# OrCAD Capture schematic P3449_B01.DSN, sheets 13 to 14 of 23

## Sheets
13 0010_USB3.1 Type-A x2 (B): size Custom
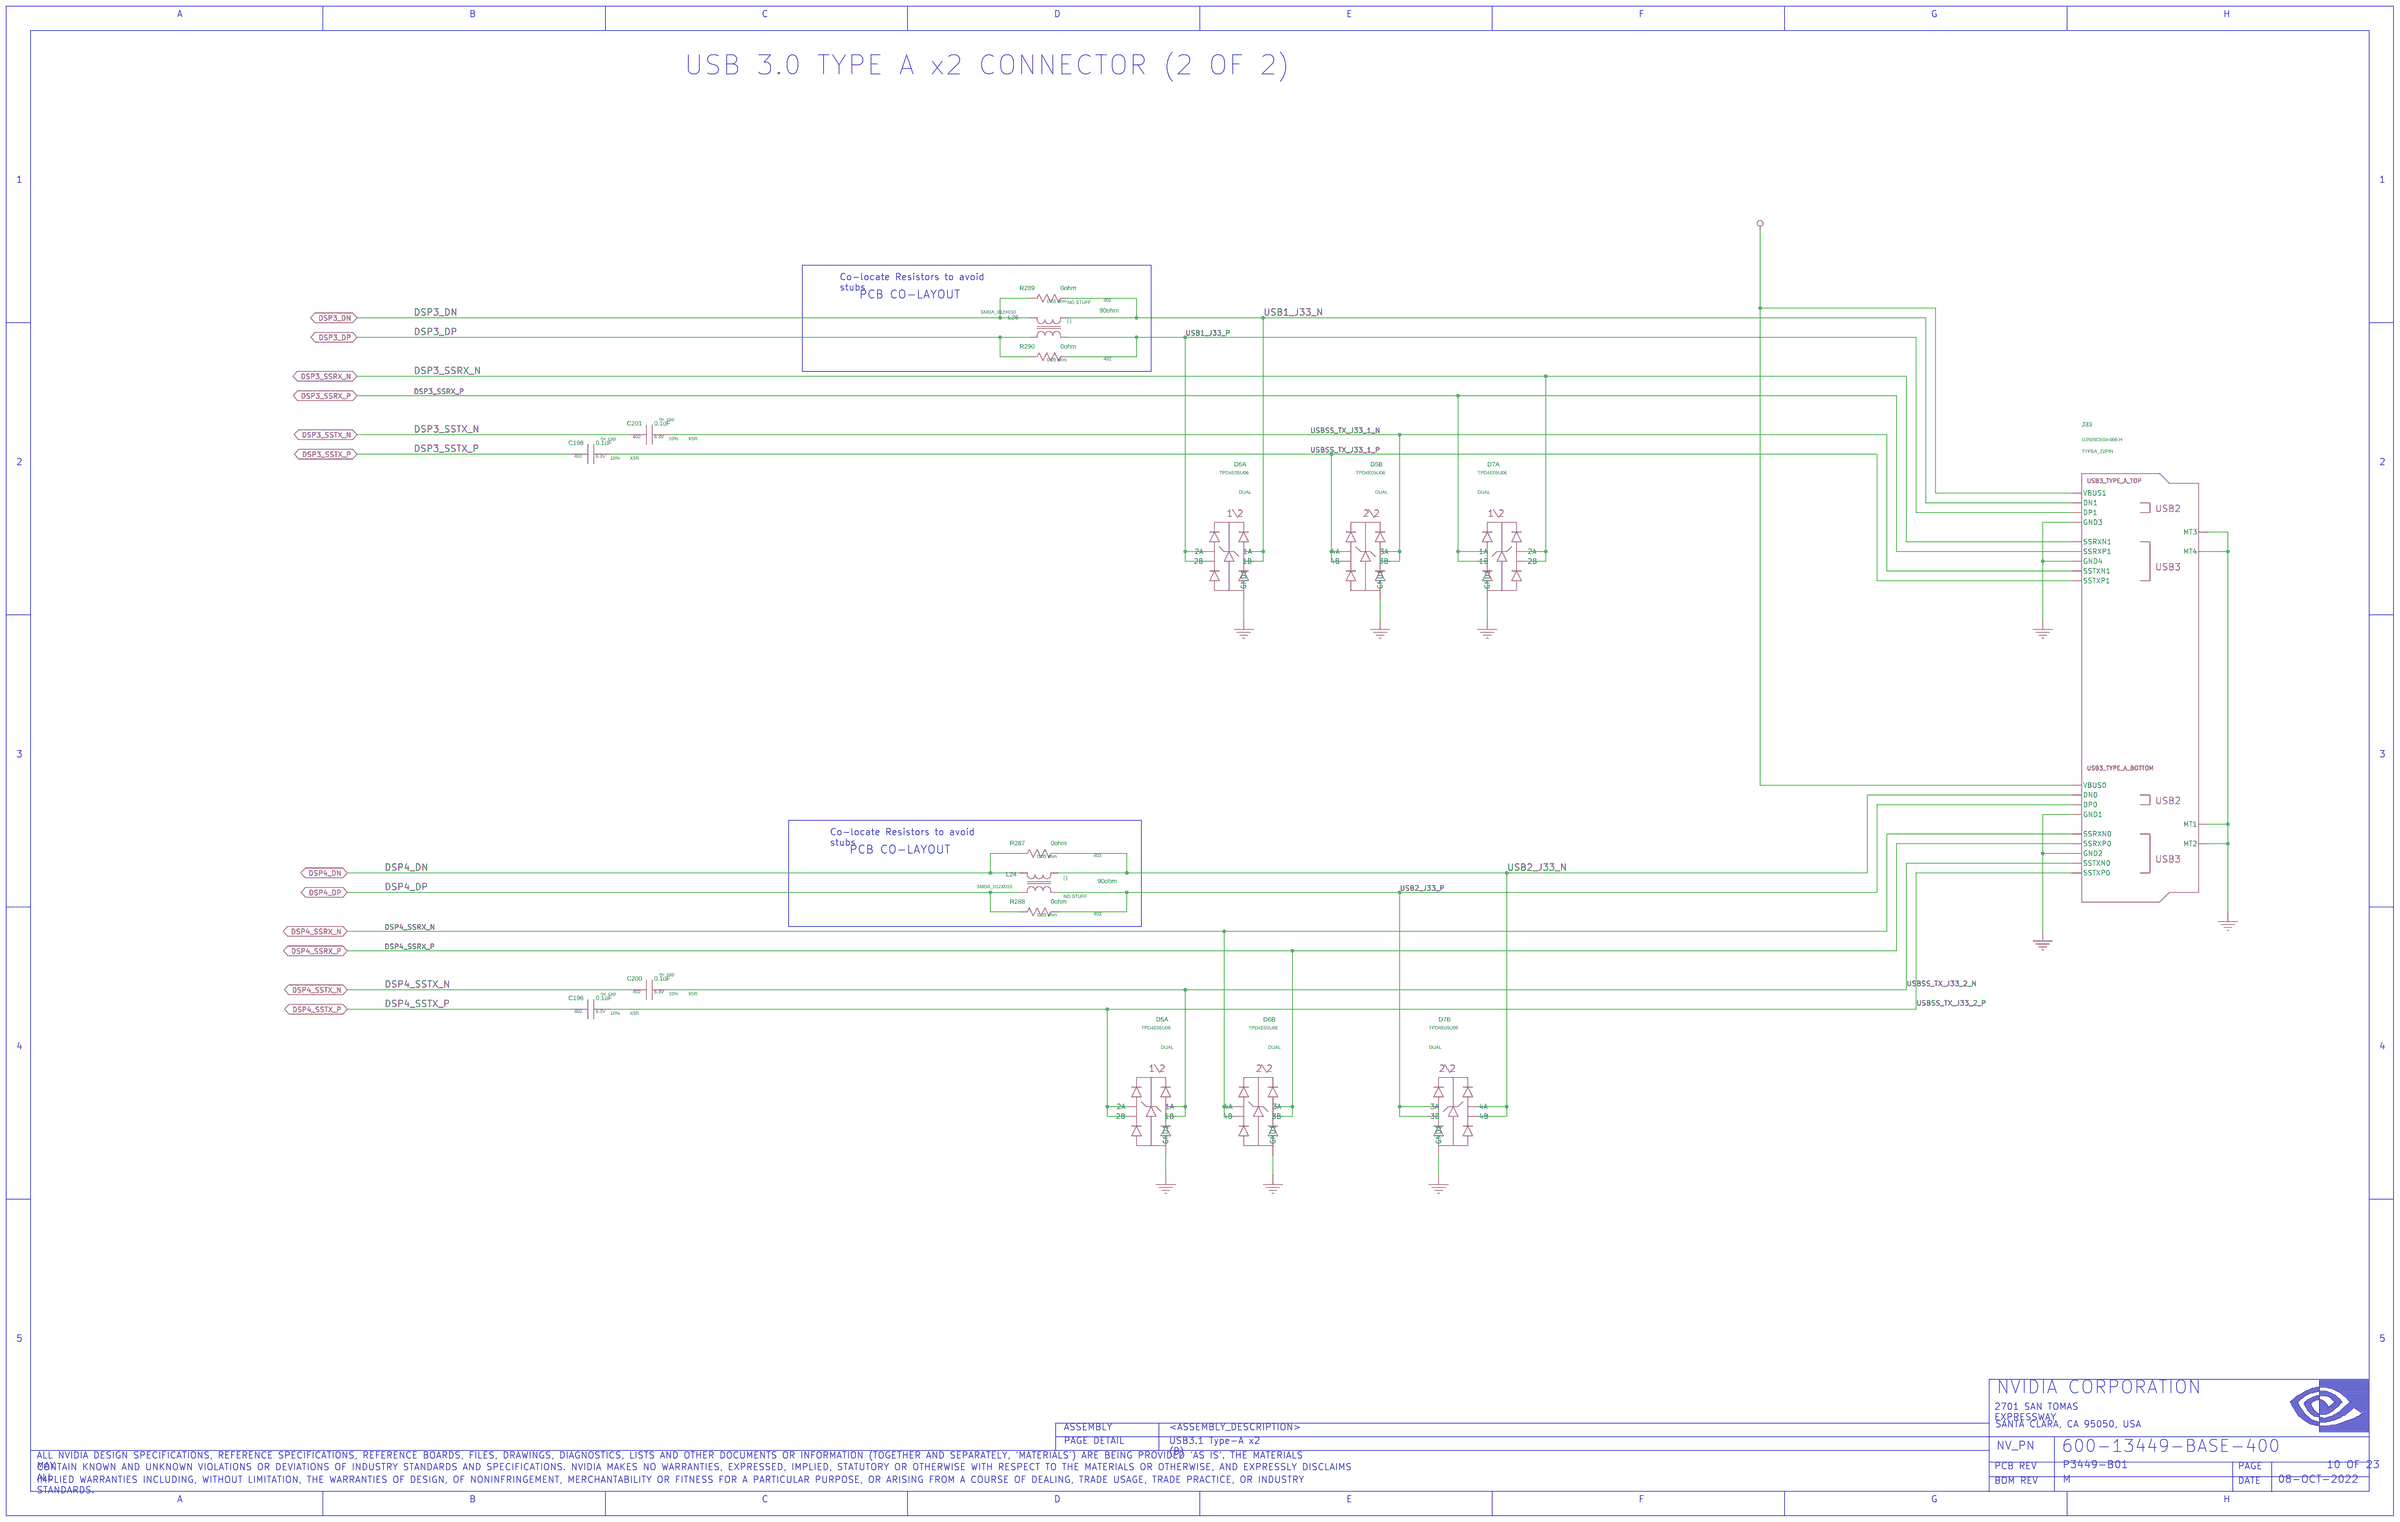
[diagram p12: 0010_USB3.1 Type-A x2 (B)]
14 0009_USB3.1 Type-A x2 (A): size Custom
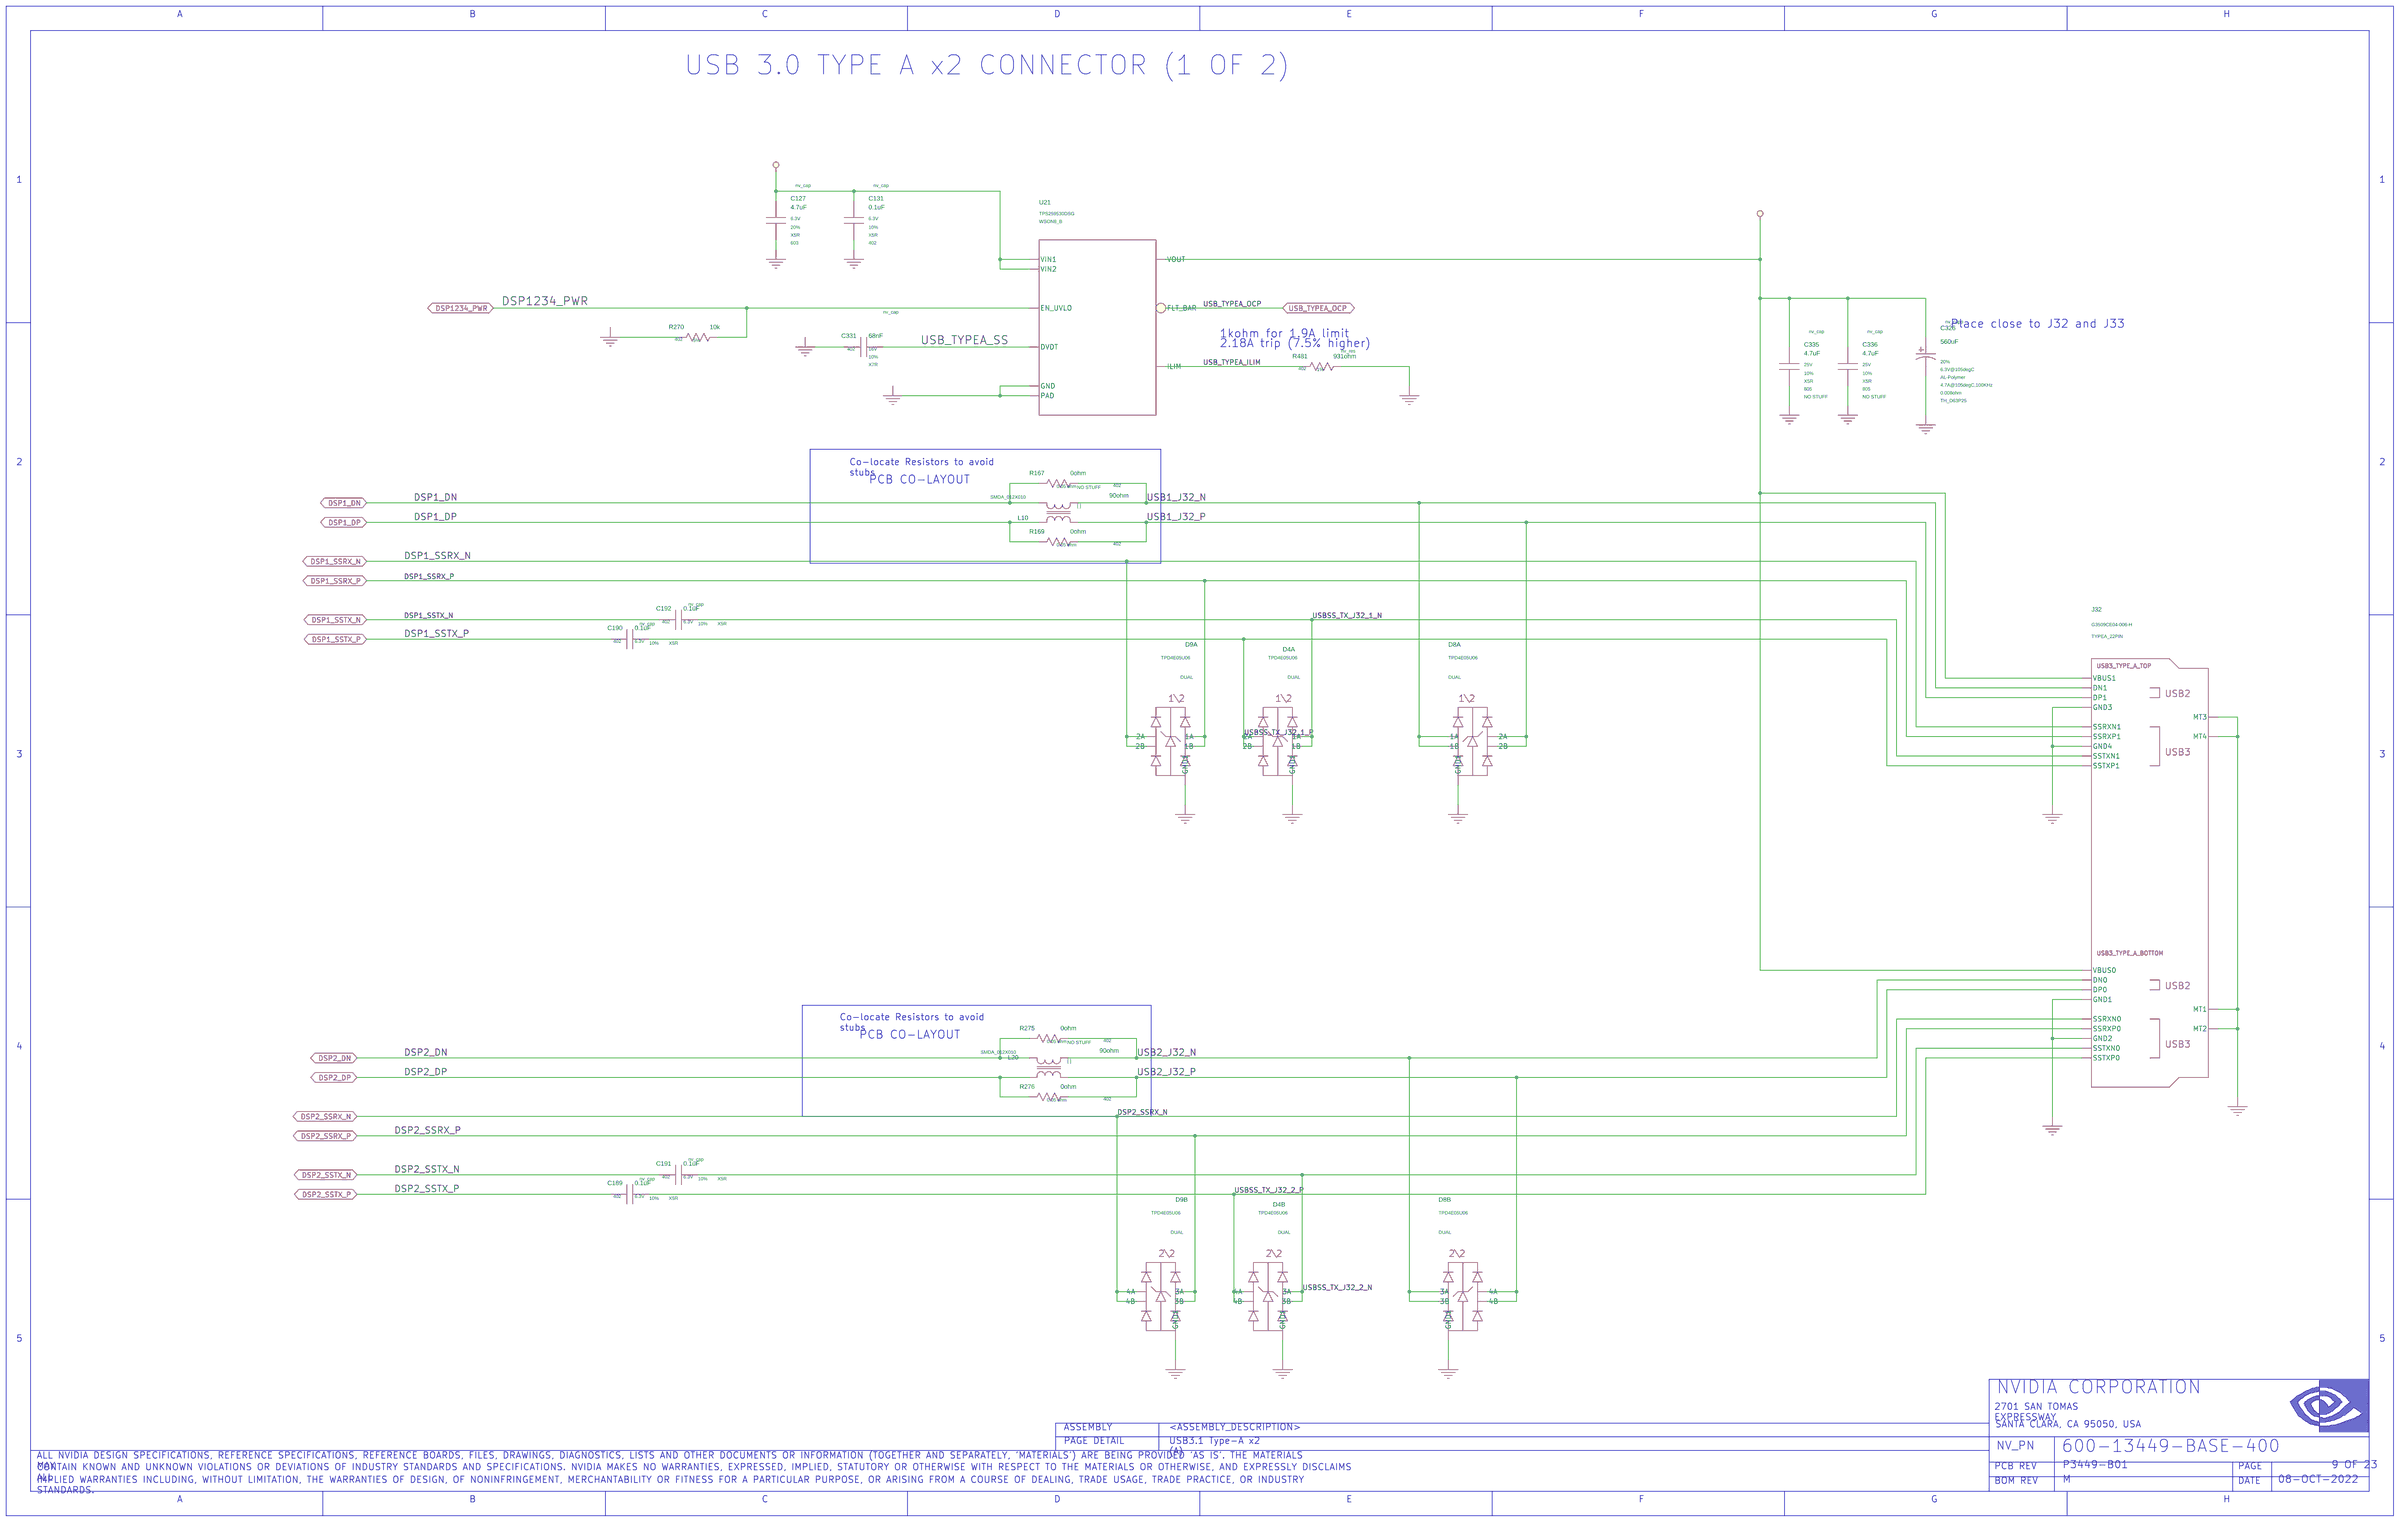
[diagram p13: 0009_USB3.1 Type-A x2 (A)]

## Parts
sheet 0009_USB3.1 Type-A x2 (A)
C127  4.7uF  [603]
C131  0.1uF  [402]
C189  0.1uF  [402]
C190  0.1uF  [402]
C191  0.1uF  [402]
C192  0.1uF  [402]
C326  560uF  [CAP_TH_D063P025]
C331  68nF  [402]
C335  4.7uF  [805]
C336  4.7uF  [805]
D4  D_ESD_DIFFPAIR  [TSLP10_P050_025X010]  (sections A,B)
D8  D_ESD_DIFFPAIR  [TSLP10_P050_025X010]  (sections A,B)
D9  D_ESD_DIFFPAIR  [TSLP10_P050_025X010]  (sections A,B)
J32  CON_USB3  [CON_USB3_018_TH_RA_134X175]
L10  90ohm  [IND_NONRKO_SMD_012X010]
L20  90ohm  [IND_NONRKO_SMD_012X010]
R167  0ohm  [402]
R169  0ohm  [402]
R270  10k  [402]
R275  0ohm  [402]
R276  0ohm  [402]
R481  931ohm  [402]
U21  U_EFUSE  [DFN08_P050_020X020_T017X010]
sheet 0010_USB3.1 Type-A x2 (B)
C196  0.1uF  [402]
C198  0.1uF  [402]
C200  0.1uF  [402]
C201  0.1uF  [402]
D5  D_ESD_DIFFPAIR  [TSLP10_P050_025X010]  (sections A,B)
D6  D_ESD_DIFFPAIR  [TSLP10_P050_025X010]  (sections A,B)
D7  D_ESD_DIFFPAIR  [TSLP10_P050_025X010]  (sections A,B)
J33  CON_USB3  [CON_USB3_018_TH_RA_134X175]
L24  90ohm  [IND_NONRKO_SMD_012X010]
L26  90ohm  [IND_NONRKO_SMD_012X010]
R287  0ohm  [402]
R288  0ohm  [402]
R289  0ohm  [402]
R290  0ohm  [402]

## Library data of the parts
C127 = C#1: ASSEMBLY: USB3_TYPEA; CDS_LIB: discrete; CDS_PART_NAME: C_0603-4.7UF,X5R,20%,6.3V,032-0886-000; CDS_PHYS_PART_NAME: C_0603-4.7UF,X5R,20%,6.3V,032-0886-000-032-0886-000,4.7UF; CDS_SEC: 1; CHIPS_PART_NAME: C; DEVICE_TYPENAME: C_0603-47UFX5R2063V032-0886-000-032-0886-00047UF; DRAWING: @P3449_B01_LIB.P3449_B01(SCH_1):PAGE9; MAT: X5R; MAX_VOLTAGE: 6.3V; NV_PN: 032-0886-000; PATH: I314; PHYS_PAGE: 9; ROT: 0; SEC: 1; SIGNAL_MODEL: nv_cap; TOL: 20%; VER: 1; XY: (-8200,6500)
C131 = C#1: ASSEMBLY: USB3_TYPEA; CDS_LIB: discrete; CDS_PART_NAME: C_0402-0.1UF,X5R,10%,6.3V,039-0007-000; CDS_PHYS_PART_NAME: C_0402-0.1UF,X5R,10%,6.3V,039-0007-000-0.1UF,039-0007-000; CDS_SEC: 1; CHIPS_PART_NAME: C; DEVICE_TYPENAME: C_0402-01UFX5R1063V039-0007-000-01UF039-0007-000; DRAWING: @P3449_B01_LIB.P3449_B01(SCH_1):PAGE9; MAT: X5R; MAX_VOLTAGE: 6.3V; NV_PN: 039-0007-000; PATH: I310; PHYS_PAGE: 9; ROT: 0; SEC: 1; SIGNAL_MODEL: nv_cap; TOL: 10%; VER: 1; XY: (-7800,6500)
C189 = C: ASSEMBLY: USB3_TYPEA; CDS_LIB: discrete; CDS_PART_NAME: C_0402-0.1UF,X5R,10%,6.3V,039-0007-000; CDS_PHYS_PART_NAME: C_0402-0.1UF,X5R,10%,6.3V,039-0007-000-0.1UF,039-0007-000; CDS_SEC: 1; DEVICE_TYPENAME: C_0402-01UFX5R1063V039-0007-000-01UF039-0007-000; DRAWING: @P3449_B01_LIB.P3449_B01(SCH_1):PAGE9; MAT: X5R; MAX_VOLTAGE: 6.3V; NV_PN: 039-0007-000; PATH: I284; PHYS_PAGE: 9; ROT: 0; SEC: 1; SIGNAL_MODEL: nv_cap; TOL: 10%; VER: 2; XY: (-8950,1500)
C190 = C: ASSEMBLY: USB3_TYPEA; CDS_LIB: discrete; CDS_PART_NAME: C_0402-0.1UF,X5R,10%,6.3V,039-0007-000; CDS_PHYS_PART_NAME: C_0402-0.1UF,X5R,10%,6.3V,039-0007-000-0.1UF,039-0007-000; CDS_SEC: 1; DEVICE_TYPENAME: C_0402-01UFX5R1063V039-0007-000-01UF039-0007-000; DRAWING: @P3449_B01_LIB.P3449_B01(SCH_1):PAGE9; MAT: X5R; MAX_VOLTAGE: 6.3V; NV_PN: 039-0007-000; PATH: I273; PHYS_PAGE: 9; ROT: 0; SEC: 1; SIGNAL_MODEL: nv_cap; TOL: 10%; VER: 2; XY: (-8950,4350)
C191 = C: ASSEMBLY: USB3_TYPEA; CDS_LIB: discrete; CDS_PART_NAME: C_0402-0.1UF,X5R,10%,6.3V,039-0007-000; CDS_PHYS_PART_NAME: C_0402-0.1UF,X5R,10%,6.3V,039-0007-000-0.1UF,039-0007-000; CDS_SEC: 1; DEVICE_TYPENAME: C_0402-01UFX5R1063V039-0007-000-01UF039-0007-000; DRAWING: @P3449_B01_LIB.P3449_B01(SCH_1):PAGE9; MAT: X5R; MAX_VOLTAGE: 6.3V; NV_PN: 039-0007-000; PATH: I285; PHYS_PAGE: 9; ROT: 0; SEC: 1; SIGNAL_MODEL: nv_cap; TOL: 10%; VER: 2; XY: (-8700,1600)
C192 = C: ASSEMBLY: USB3_TYPEA; CDS_LIB: discrete; CDS_PART_NAME: C_0402-0.1UF,X5R,10%,6.3V,039-0007-000; CDS_PHYS_PART_NAME: C_0402-0.1UF,X5R,10%,6.3V,039-0007-000-0.1UF,039-0007-000; CDS_SEC: 1; DEVICE_TYPENAME: C_0402-01UFX5R1063V039-0007-000-01UF039-0007-000; DRAWING: @P3449_B01_LIB.P3449_B01(SCH_1):PAGE9; MAT: X5R; MAX_VOLTAGE: 6.3V; NV_PN: 039-0007-000; PATH: I272; PHYS_PAGE: 9; ROT: 0; SEC: 1; SIGNAL_MODEL: nv_cap; TOL: 10%; VER: 2; XY: (-8700,4450)
C326 = C_POL: ASSEMBLY: USB3_TYPEA; CDS_LIB: discrete; CDS_PART_NAME: C_POL_TH_D63P25-560UF,AL-POLYMER,20%,6.3V@105DEGC,0.008OHM,0.999UH,4.7A@105DEGC,100KHZ,032-1441-000; CDS_PHYS_PART_NAME: C_POL_TH_D63P25-560UF,AL-POLYMER,20%,6.3V@105DEGC,0.008OHM,0.999UH,4.7A@105DEGC,100KHZ,032-1441-000-032-1441-000,560UF; CDS_SEC: 1; DEVICE_TYPENAME: C_POL_TH_D63P25-560UFAL-POLYMER2063V105DEGC0008OHM0999UH47A105DEGC100KHZ032-1441-000-032-1441-000560UF; DRAWING: @P3449_B01_LIB.P3449_B01(SCH_1):PAGE9; ESL: 0.999uH; ESR: 0.008ohm; MAT: AL-Polymer; MAX_VOLTAGE: 6.3V@105degC; NV_PN: 032-1441-000; PACK_TYPE: TH_D63P25; PATH: I325; PHYS_PAGE: 9; PLACEMENT_NOTE: Place close to J32 and J33; RIPPLE_CURRENT: 4.7A@105degC,100KHz; ROT: 0; SEC: 1; SIGNAL_MODEL: nv_capp; TOL: 20%; VER: 1; XY: (-2300,5800)
C331 = C: ASSEMBLY: USB3_TYPEA; CDS_LIB: discrete; CDS_PART_NAME: C_0402-68NF,X7R,10%,16V,036-0254-000; CDS_PHYS_PART_NAME: C_0402-68NF,X7R,10%,16V,036-0254-000-036-0254-000,68NF; CDS_SEC: 1; DEVICE_TYPENAME: C_0402-68NFX7R1016V036-0254-000-036-0254-00068NF; DRAWING: @P3449_B01_LIB.P3449_B01(SCH_1):PAGE9; MAT: X7R; MAX_VOLTAGE: 16V; NV_PN: 036-0254-000; PATH: I330; PHYS_PAGE: 9; ROT: 0; SEC: 1; SIGNAL_MODEL: nv_cap; TOL: 10%; VER: 2; XY: (-7750,5850)
C335 = C#1: ASSEMBLY: USB3_TYPEA; CDS_LIB: discrete; CDS_PART_NAME: C_0805-4.7UF,X5R,10%,25V,032-1141-000; CDS_PHYS_PART_NAME: C_0805-4.7UF,X5R,10%,25V,032-1141-000-032-1141-000,4.7UF; CDS_SEC: 1; CHIPS_PART_NAME: C; DEVICE_TYPENAME: C_0805-47UFX5R1025V032-1141-000-032-1141-00047UF; DRAWING: @P3449_B01_LIB.P3449_B01(SCH_1):PAGE9; IMPLEMENTATION_TYPE: X^@REFDES  %1    %2   @NV_PN; MAT: X5R; MAX_VOLTAGE: 25V; NV_PN: 032-1141-000; PATH: I336; PHYS_PAGE: 9; PSPICETEMPLATE: Pspice Model; ROT: 0; SEC: 1; SIGNAL_MODEL: nv_cap; SKU: NO STUFF; TOL: 10%; VER: 1; XY: (-3000,5750)
C336 = C#1: ASSEMBLY: USB3_TYPEA; CDS_LIB: discrete; CDS_PART_NAME: C_0805-4.7UF,X5R,10%,25V,032-1141-000; CDS_PHYS_PART_NAME: C_0805-4.7UF,X5R,10%,25V,032-1141-000-032-1141-000,4.7UF; CDS_SEC: 1; CHIPS_PART_NAME: C; DEVICE_TYPENAME: C_0805-47UFX5R1025V032-1141-000-032-1141-00047UF; DRAWING: @P3449_B01_LIB.P3449_B01(SCH_1):PAGE9; IMPLEMENTATION_TYPE: X^@REFDES  %1    %2   @NV_PN; MAT: X5R; MAX_VOLTAGE: 25V; NV_PN: 032-1141-000; PATH: I335; PHYS_PAGE: 9; PSPICETEMPLATE: Pspice Model; ROT: 0; SEC: 1; SIGNAL_MODEL: nv_cap; SKU: NO STUFF; TOL: 10%; VER: 1; XY: (-2700,5750)
D4 = D_ESD_DIFFPAIR: ASSEMBLY: USB3_TYPEA; BREAKDOWN_VOLTAGE_MIN_TYP: 6V; CAPACITANCE_MAX_TYP: 0.5pF; CDS_LIB: discrete; CDS_PART_NAME: D_ESD_DIFFPAIR_DUAL-TPD4E05U06,2 DIFFPAIR,UNI-DIRECTIONAL,5.5V,10UA,6V,10V@1A,0.5PF,090-0231-000; CDS_PHYS_PART_NAME: D_ESD_DIFFPAIR_DUAL-TPD4E05U06,2 DIFFPAIR,UNI-DIRECTIONAL,5.5V,10UA,6V,10V@1A,0.5PF,090-0231-000-090-0231-000; CDS_SEC: 1; CLAMPING_VOLTAGE: 10V@1A; CONFIGURATION: 2 Diffpair; CaptureCellPackProp: D_ESD_DIFFPAIRA; DEVICE_TYPENAME: D_ESD_DIFFPAIR_DUAL-TPD4E05U062DIFFPAIRUNI-DIRECTIONAL55V10UA6V10V1A05PF090-0231-000-090-0231-000; DRAWING: @P3449_B01_LIB.P3449_B01(SCH_1):PAGE9; MAX_REVERSE_LEAKAGE_CURRENT: 10uA; MAX_REVERSE_VOLTAGE: 5.5V; NV_NAME: TPD4E05U06; NV_PN: 090-0231-000; PACK_TYPE: DUAL; PATH: I280; PHYS_PAGE: 9; POLARITY: Uni-Directional; ROT: 2; SEC: 1; VER: 1; XY: (-5600,3850)
D8 = D_ESD_DIFFPAIR: ASSEMBLY: USB3_TYPEA; BREAKDOWN_VOLTAGE_MIN_TYP: 6V; CAPACITANCE_MAX_TYP: 0.5pF; CDS_LIB: discrete; CDS_PART_NAME: D_ESD_DIFFPAIR_DUAL-TPD4E05U06,2 DIFFPAIR,UNI-DIRECTIONAL,5.5V,10UA,6V,10V@1A,0.5PF,090-0231-000; CDS_PHYS_PART_NAME: D_ESD_DIFFPAIR_DUAL-TPD4E05U06,2 DIFFPAIR,UNI-DIRECTIONAL,5.5V,10UA,6V,10V@1A,0.5PF,090-0231-000-090-0231-000; CDS_SEC: 2; CLAMPING_VOLTAGE: 10V@1A; CONFIGURATION: 2 Diffpair; CaptureCellPackProp: D_ESD_DIFFPAIRB; DEVICE_TYPENAME: D_ESD_DIFFPAIR_DUAL-TPD4E05U062DIFFPAIRUNI-DIRECTIONAL55V10UA6V10V1A05PF090-0231-000-090-0231-000; DRAWING: @P3449_B01_LIB.P3449_B01(SCH_1):PAGE9; MAX_REVERSE_LEAKAGE_CURRENT: 10uA; MAX_REVERSE_VOLTAGE: 5.5V; NV_NAME: TPD4E05U06; NV_PN: 090-0231-000; PACK_TYPE: DUAL; PATH: I217; PHYS_PAGE: 9; POLARITY: Uni-Directional; ROT: 0; SEC: 2; SEC_TYPE: DUAL; VER: 2; XY: (-4700,1000)
D9 = D_ESD_DIFFPAIR: ASSEMBLY: USB3_TYPEA; BREAKDOWN_VOLTAGE_MIN_TYP: 6V; CAPACITANCE_MAX_TYP: 0.5pF; CDS_LIB: discrete; CDS_PART_NAME: D_ESD_DIFFPAIR_DUAL-TPD4E05U06,2 DIFFPAIR,UNI-DIRECTIONAL,5.5V,10UA,6V,10V@1A,0.5PF,090-0231-000; CDS_PHYS_PART_NAME: D_ESD_DIFFPAIR_DUAL-TPD4E05U06,2 DIFFPAIR,UNI-DIRECTIONAL,5.5V,10UA,6V,10V@1A,0.5PF,090-0231-000-090-0231-000; CDS_SEC: 1; CLAMPING_VOLTAGE: 10V@1A; CONFIGURATION: 2 Diffpair; CaptureCellPackProp: D_ESD_DIFFPAIRA; DEVICE_TYPENAME: D_ESD_DIFFPAIR_DUAL-TPD4E05U062DIFFPAIRUNI-DIRECTIONAL55V10UA6V10V1A05PF090-0231-000-090-0231-000; DRAWING: @P3449_B01_LIB.P3449_B01(SCH_1):PAGE9; MAX_REVERSE_LEAKAGE_CURRENT: 10uA; MAX_REVERSE_VOLTAGE: 5.5V; NV_NAME: TPD4E05U06; NV_PN: 090-0231-000; PACK_TYPE: DUAL; PATH: I62; PHYS_PAGE: 9; POLARITY: Uni-Directional; ROT: 2; SEC: 1; VER: 1; XY: (-6150,3850)
J32 = CON_USB3#1: ANGLE: 90; ASSEMBLY: USB3_TYPEA; CDS_LIB: electro_mechanic; CDS_PART_NAME: CON_USB3_TYPEA_22PIN-G3509CE04-006-H,RECEPTACLE,2MM,90,YES,NO,YES,NO,YES,5.0 V,1.8 A,065-0656-000; CDS_PHYS_PART_NAME: CON_USB3_TYPEA_22PIN-G3509CE04-006-H,RECEPTACLE,2MM,90,YES,NO,YES,NO,YES,5.0 V,1.8 A,065-0656-000-065-0656-000; CDS_SEC: 1; DEVICE_TYPENAME: CON_USB3_TYPEA_22PIN-G3509CE04-006-HRECEPTACLE2MM90YESNOYESNOYES50V18A065-0656-000-065-0656-000; DRAWING: @P3449_B01_LIB.P3449_B01(SCH_1):PAGE9; EMI_GROUND_TAB: NO; GENDER: Receptacle; LATCHING: YES; MAX_CURRENT: 1.8 A; MAX_VOLTAGE: 5.0 V; NV_NAME: G3509CE04-006-H; NV_PN: 065-0656-000; PACK_TYPE: TYPEA_22PIN; PATH: I296; PHYS_PAGE: 9; PITCH: 2mm; REFLOW: YES; ROT: 0; SEC: 1; SHIELDED: YES; SHROUDED: No; VER: 5; XY: (-1150,3900)
L10 = L_CMF_4P: ASSEMBLY: USB3_TYPEA; CDS_LIB: discrete; CDS_PART_NAME: L_CMF_4P_SMDA_012X010-90OHM,[ ],25%,0.2A,0.4OHM,[ ],102-0037-000; CDS_PHYS_PART_NAME: L_CMF_4P_SMDA_012X010-90OHM,[ ],25%,0.2A,0.4OHM,[ ],102-0037-000-102-0037-000,90OHM; CDS_SEC: 1; DC_RESISTANCE: 0.4ohm; DEVICE_TYPENAME: L_CMF_4P_SMDA_012X010-90OHM2502A04OHM102-0037-000-102-0037-00090OHM; DRAWING: @P3449_B01_LIB.P3449_B01(SCH_1):PAGE9; MAT: [ ]; MAX_CURRENT: 0.2A; NV_NAME: [ ]; NV_PN: 102-0037-000; PACK_TYPE: SMDA_012X010; PATH: I191; PHYS_PAGE: 9; PLACEMENT_NOTE: CoLayout with R167, R169; ROT: 0; SEC: 1; SEC_TYPE: SMDA_012X010; SIGNAL_MODEL: nv_ind_cmf_4p; SKU: NO STUFF; TOL: 25%; VER: 3; XY: (-6750,5000)
L20 = L_CMF_4P: ASSEMBLY: USB3_TYPEA; CDS_LIB: discrete; CDS_PART_NAME: L_CMF_4P_SMDA_012X010-90OHM,[ ],25%,0.2A,0.4OHM,[ ],102-0037-000; CDS_PHYS_PART_NAME: L_CMF_4P_SMDA_012X010-90OHM,[ ],25%,0.2A,0.4OHM,[ ],102-0037-000-102-0037-000,90OHM; CDS_SEC: 1; DC_RESISTANCE: 0.4ohm; DEVICE_TYPENAME: L_CMF_4P_SMDA_012X010-90OHM2502A04OHM102-0037-000-102-0037-00090OHM; DRAWING: @P3449_B01_LIB.P3449_B01(SCH_1):PAGE9; MAT: [ ]; MAX_CURRENT: 0.2A; NV_NAME: [ ]; NV_PN: 102-0037-000; PACK_TYPE: SMDA_012X010; PATH: I293; PHYS_PAGE: 9; PLACEMENT_NOTE: CoLayout with R167, R169; ROT: 0; SEC: 1; SEC_TYPE: SMDA_012X010; SIGNAL_MODEL: nv_ind_cmf_4p; SKU: NO STUFF; TOL: 25%; VER: 3; XY: (-6800,2150)
R167 = R#1: ASSEMBLY: USB3_TYPEA; CDS_LIB: discrete; CDS_PART_NAME: R_0402-0OHM,0.05 OHM,62.5MW,195-2655-000; CDS_PHYS_PART_NAME: R_0402-0OHM,0.05 OHM,62.5MW,195-2655-000-0OHM,195-2655-000; CDS_SEC: 1; CHIPS_PART_NAME: R; DEVICE_TYPENAME: R_0402-0OHM005OHM625MW195-2655-000-0OHM195-2655-000; DRAWING: @P3449_B01_LIB.P3449_B01(SCH_1):PAGE9; MAX_WATTAGE: 62.5mW; NV_PN: 195-2655-000; PATH: I59; PHYS_PAGE: 9; PLACEMENT_NOTE: CoLayout with L10; ROT: 0; SEC: 1; SIGNAL_MODEL: DEFAULT_RESISTOR_0.001OHM_2_1; TOL: 0.05 ohm; VER: 1; XY: (-6750,5150)
R169 = R#1: ASSEMBLY: USB3_TYPEA; CDS_LIB: discrete; CDS_PART_NAME: R_0402-0OHM,0.05 OHM,62.5MW,195-2655-000; CDS_PHYS_PART_NAME: R_0402-0OHM,0.05 OHM,62.5MW,195-2655-000-0OHM,195-2655-000; CDS_SEC: 1; CHIPS_PART_NAME: R; DEVICE_TYPENAME: R_0402-0OHM005OHM625MW195-2655-000-0OHM195-2655-000; DRAWING: @P3449_B01_LIB.P3449_B01(SCH_1):PAGE9; MAX_WATTAGE: 62.5mW; NV_PN: 195-2655-000; PATH: I58; PHYS_PAGE: 9; PLACEMENT_NOTE: CoLayout with L10; ROT: 0; SEC: 1; SIGNAL_MODEL: DEFAULT_RESISTOR_0.001OHM_2_1; TOL: 0.05 ohm; VER: 1; XY: (-6750,4850)
R270 = R#1: ASSEMBLY: USB3_TYPEA; CDS_LIB: discrete; CDS_PART_NAME: R_0402-10K,5 %,62.5MW,195-0486-000; CDS_PHYS_PART_NAME: R_0402-10K,5 %,62.5MW,195-0486-000-10K,195-0486-000; CDS_SEC: 1; CHIPS_PART_NAME: R; DEVICE_TYPENAME: R_0402-10K5625MW195-0486-000-10K195-0486-000; DRAWING: @P3449_B01_LIB.P3449_B01(SCH_1):PAGE9; MAX_WATTAGE: 62.5mW; NV_PN: 195-0486-000; PATH: I308; PHYS_PAGE: 9; ROT: 0; SEC: 1; SIGNAL_MODEL: nv_res; TOL: 5%; VER: 1; XY: (-8600,5900)
R275 = R#1: ASSEMBLY: USB3_TYPEA; CDS_LIB: discrete; CDS_PART_NAME: R_0402-0OHM,0.05 OHM,62.5MW,195-2655-000; CDS_PHYS_PART_NAME: R_0402-0OHM,0.05 OHM,62.5MW,195-2655-000-0OHM,195-2655-000; CDS_SEC: 1; CHIPS_PART_NAME: R; DEVICE_TYPENAME: R_0402-0OHM005OHM625MW195-2655-000-0OHM195-2655-000; DRAWING: @P3449_B01_LIB.P3449_B01(SCH_1):PAGE9; MAX_WATTAGE: 62.5mW; NV_PN: 195-2655-000; PATH: I294; PHYS_PAGE: 9; PLACEMENT_NOTE: CoLayout with L10; ROT: 0; SEC: 1; SIGNAL_MODEL: DEFAULT_RESISTOR_0.001OHM_2_1; TOL: 0.05 ohm; VER: 1; XY: (-6800,2300)
R276 = R#1: ASSEMBLY: USB3_TYPEA; CDS_LIB: discrete; CDS_PART_NAME: R_0402-0OHM,0.05 OHM,62.5MW,195-2655-000; CDS_PHYS_PART_NAME: R_0402-0OHM,0.05 OHM,62.5MW,195-2655-000-0OHM,195-2655-000; CDS_SEC: 1; CHIPS_PART_NAME: R; DEVICE_TYPENAME: R_0402-0OHM005OHM625MW195-2655-000-0OHM195-2655-000; DRAWING: @P3449_B01_LIB.P3449_B01(SCH_1):PAGE9; MAX_WATTAGE: 62.5mW; NV_PN: 195-2655-000; PATH: I292; PHYS_PAGE: 9; PLACEMENT_NOTE: CoLayout with L10; ROT: 0; SEC: 1; SIGNAL_MODEL: DEFAULT_RESISTOR_0.001OHM_2_1; TOL: 0.05 ohm; VER: 1; XY: (-6800,2000)
R481 = R#1: ASSEMBLY: USB3_TYPEA; CDS_LIB: discrete; CDS_PART_NAME: R_0402-931OHM,1 %,62.5MW,195-0468-000; CDS_PHYS_PART_NAME: R_0402-931OHM,1 %,62.5MW,195-0468-000-195-0468-000,931OHM; CDS_SEC: 1; CHIPS_PART_NAME: R; DEVICE_TYPENAME: R_0402-931OHM1625MW195-0468-000-195-0468-000931OHM; DRAWING: @P3449_B01_LIB.P3449_B01(SCH_1):PAGE9; MAX_WATTAGE: 62.5mW; NV_PN: 195-0468-000; PATH: I332; PHYS_PAGE: 9; ROT: 0; SEC: 1; SIGNAL_MODEL: nv_res; TOL: 1%; VER: 1; XY: (-5400,5750)
U21 = U_EFUSE: ASSEMBLY: USB3_TYPEA; CDS_LIB: power_supply; CDS_PART_NAME: U_EFUSE_WSON8_B-TPS259530DSG,0MV..18V,2.7V..18V,4A,OTHER,315-1117-000; CDS_PHYS_PART_NAME: U_EFUSE_WSON8_B-TPS259530DSG,0MV..18V,2.7V..18V,4A,OTHER,315-1117-000-315-1117-000; CDS_SEC: 1; DEVICE_TYPENAME: U_EFUSE_WSON8_B-TPS259530DSG0MV18V27V18V4AOTHER315-1117-000-315-1117-000; DRAWING: @P3449_B01_LIB.P3449_B01(SCH_1):PAGE9; MAX_CURRENT: 4A; MAX_VOLTAGE: 2.7V..18V; NV_NAME: TPS259530DSG; NV_PN: 315-1117-000; OUTPUT_VOLTAGE: 0mV..18V; PACK_TYPE: WSON8_B; PATH: I334; PHYS_PAGE: 9; ROT: 0; SEC: 1; TYPE: Other; VER: 4; XY: (-6550,5950)
C196 = C: ASSEMBLY: USB3_TYPEA; CDS_LIB: discrete; CDS_PART_NAME: C_0402-0.1UF,X5R,10%,6.3V,039-0007-000; CDS_PHYS_PART_NAME: C_0402-0.1UF,X5R,10%,6.3V,039-0007-000-0.1UF,039-0007-000; CDS_SEC: 1; DEVICE_TYPENAME: C_0402-01UFX5R1063V039-0007-000-01UF039-0007-000; DRAWING: @P3449_B01_LIB.P3449_B01(SCH_1):PAGE10; MAT: X5R; MAX_VOLTAGE: 6.3V; NV_PN: 039-0007-000; PATH: I44; PHYS_PAGE: 10; ROT: 0; SEC: 1; SIGNAL_MODEL: nv_cap; TOL: 10%; VER: 2; XY: (-9150,2450)
C198 = C: ASSEMBLY: USB3_TYPEA; CDS_LIB: discrete; CDS_PART_NAME: C_0402-0.1UF,X5R,10%,6.3V,039-0007-000; CDS_PHYS_PART_NAME: C_0402-0.1UF,X5R,10%,6.3V,039-0007-000-0.1UF,039-0007-000; CDS_SEC: 1; DEVICE_TYPENAME: C_0402-01UFX5R1063V039-0007-000-01UF039-0007-000; DRAWING: @P3449_B01_LIB.P3449_B01(SCH_1):PAGE10; MAT: X5R; MAX_VOLTAGE: 6.3V; NV_PN: 039-0007-000; PATH: I35; PHYS_PAGE: 10; ROT: 0; SEC: 1; SIGNAL_MODEL: nv_cap; TOL: 10%; VER: 2; XY: (-9150,5300)
C200 = C: ASSEMBLY: USB3_TYPEA; CDS_LIB: discrete; CDS_PART_NAME: C_0402-0.1UF,X5R,10%,6.3V,039-0007-000; CDS_PHYS_PART_NAME: C_0402-0.1UF,X5R,10%,6.3V,039-0007-000-0.1UF,039-0007-000; CDS_SEC: 1; DEVICE_TYPENAME: C_0402-01UFX5R1063V039-0007-000-01UF039-0007-000; DRAWING: @P3449_B01_LIB.P3449_B01(SCH_1):PAGE10; MAT: X5R; MAX_VOLTAGE: 6.3V; NV_PN: 039-0007-000; PATH: I43; PHYS_PAGE: 10; ROT: 0; SEC: 1; SIGNAL_MODEL: nv_cap; TOL: 10%; VER: 2; XY: (-8850,2550)
C201 = C: ASSEMBLY: USB3_TYPEA; CDS_LIB: discrete; CDS_PART_NAME: C_0402-0.1UF,X5R,10%,6.3V,039-0007-000; CDS_PHYS_PART_NAME: C_0402-0.1UF,X5R,10%,6.3V,039-0007-000-0.1UF,039-0007-000; CDS_SEC: 1; DEVICE_TYPENAME: C_0402-01UFX5R1063V039-0007-000-01UF039-0007-000; DRAWING: @P3449_B01_LIB.P3449_B01(SCH_1):PAGE10; MAT: X5R; MAX_VOLTAGE: 6.3V; NV_PN: 039-0007-000; PATH: I34; PHYS_PAGE: 10; ROT: 0; SEC: 1; SIGNAL_MODEL: nv_cap; TOL: 10%; VER: 2; XY: (-8850,5400)
D5 = D_ESD_DIFFPAIR: ASSEMBLY: USB3_TYPEA; BREAKDOWN_VOLTAGE_MIN_TYP: 6V; CAPACITANCE_MAX_TYP: 0.5pF; CDS_LIB: discrete; CDS_PART_NAME: D_ESD_DIFFPAIR_DUAL-TPD4E05U06,2 DIFFPAIR,UNI-DIRECTIONAL,5.5V,10UA,6V,10V@1A,0.5PF,090-0231-000; CDS_PHYS_PART_NAME: D_ESD_DIFFPAIR_DUAL-TPD4E05U06,2 DIFFPAIR,UNI-DIRECTIONAL,5.5V,10UA,6V,10V@1A,0.5PF,090-0231-000-090-0231-000; CDS_SEC: 1; CLAMPING_VOLTAGE: 10V@1A; CONFIGURATION: 2 Diffpair; CaptureCellPackProp: D_ESD_DIFFPAIRA; DEVICE_TYPENAME: D_ESD_DIFFPAIR_DUAL-TPD4E05U062DIFFPAIRUNI-DIRECTIONAL55V10UA6V10V1A05PF090-0231-000-090-0231-000; DRAWING: @P3449_B01_LIB.P3449_B01(SCH_1):PAGE10; MAX_REVERSE_LEAKAGE_CURRENT: 10uA; MAX_REVERSE_VOLTAGE: 5.5V; NV_NAME: TPD4E05U06; NV_PN: 090-0231-000; PACK_TYPE: DUAL; PATH: I32; PHYS_PAGE: 10; POLARITY: Uni-Directional; ROT: 2; SEC: 1; VER: 1; XY: (-6250,1950)
D6 = D_ESD_DIFFPAIR: ASSEMBLY: USB3_TYPEA; BREAKDOWN_VOLTAGE_MIN_TYP: 6V; CAPACITANCE_MAX_TYP: 0.5pF; CDS_LIB: discrete; CDS_PART_NAME: D_ESD_DIFFPAIR_DUAL-TPD4E05U06,2 DIFFPAIR,UNI-DIRECTIONAL,5.5V,10UA,6V,10V@1A,0.5PF,090-0231-000; CDS_PHYS_PART_NAME: D_ESD_DIFFPAIR_DUAL-TPD4E05U06,2 DIFFPAIR,UNI-DIRECTIONAL,5.5V,10UA,6V,10V@1A,0.5PF,090-0231-000-090-0231-000; CDS_SEC: 1; CLAMPING_VOLTAGE: 10V@1A; CONFIGURATION: 2 Diffpair; CaptureCellPackProp: D_ESD_DIFFPAIRA; DEVICE_TYPENAME: D_ESD_DIFFPAIR_DUAL-TPD4E05U062DIFFPAIRUNI-DIRECTIONAL55V10UA6V10V1A05PF090-0231-000-090-0231-000; DRAWING: @P3449_B01_LIB.P3449_B01(SCH_1):PAGE10; MAX_REVERSE_LEAKAGE_CURRENT: 10uA; MAX_REVERSE_VOLTAGE: 5.5V; NV_NAME: TPD4E05U06; NV_PN: 090-0231-000; PACK_TYPE: DUAL; PATH: I10; PHYS_PAGE: 10; POLARITY: Uni-Directional; ROT: 2; SEC: 1; VER: 1; XY: (-5850,4800)
D7 = D_ESD_DIFFPAIR: ASSEMBLY: USB3_TYPEA; BREAKDOWN_VOLTAGE_MIN_TYP: 6V; CAPACITANCE_MAX_TYP: 0.5pF; CDS_LIB: discrete; CDS_PART_NAME: D_ESD_DIFFPAIR_DUAL-TPD4E05U06,2 DIFFPAIR,UNI-DIRECTIONAL,5.5V,10UA,6V,10V@1A,0.5PF,090-0231-000; CDS_PHYS_PART_NAME: D_ESD_DIFFPAIR_DUAL-TPD4E05U06,2 DIFFPAIR,UNI-DIRECTIONAL,5.5V,10UA,6V,10V@1A,0.5PF,090-0231-000-090-0231-000; CDS_SEC: 1; CLAMPING_VOLTAGE: 10V@1A; CONFIGURATION: 2 Diffpair; CaptureCellPackProp: D_ESD_DIFFPAIRA; DEVICE_TYPENAME: D_ESD_DIFFPAIR_DUAL-TPD4E05U062DIFFPAIRUNI-DIRECTIONAL55V10UA6V10V1A05PF090-0231-000-090-0231-000; DRAWING: @P3449_B01_LIB.P3449_B01(SCH_1):PAGE10; MAX_REVERSE_LEAKAGE_CURRENT: 10uA; MAX_REVERSE_VOLTAGE: 5.5V; NV_NAME: TPD4E05U06; NV_PN: 090-0231-000; PACK_TYPE: DUAL; PATH: I5; PHYS_PAGE: 10; POLARITY: Uni-Directional; ROT: 0; SEC: 1; VER: 1; XY: (-4500,4800)
J33 = CON_USB3#1: ANGLE: 90; ASSEMBLY: USB3_TYPEA; CDS_LIB: electro_mechanic; CDS_PART_NAME: CON_USB3_TYPEA_22PIN-G3509CE04-006-H,RECEPTACLE,2MM,90,YES,NO,YES,NO,YES,5.0 V,1.8 A,065-0656-000; CDS_PHYS_PART_NAME: CON_USB3_TYPEA_22PIN-G3509CE04-006-H,RECEPTACLE,2MM,90,YES,NO,YES,NO,YES,5.0 V,1.8 A,065-0656-000-065-0656-000; CDS_SEC: 1; DEVICE_TYPENAME: CON_USB3_TYPEA_22PIN-G3509CE04-006-HRECEPTACLE2MM90YESNOYESNOYES50V18A065-0656-000-065-0656-000; DRAWING: @P3449_B01_LIB.P3449_B01(SCH_1):PAGE10; EMI_GROUND_TAB: NO; GENDER: Receptacle; LATCHING: YES; MAX_CURRENT: 1.8 A; MAX_VOLTAGE: 5.0 V; NV_NAME: G3509CE04-006-H; NV_PN: 065-0656-000; PACK_TYPE: TYPEA_22PIN; PATH: I3; PHYS_PAGE: 10; PITCH: 2mm; REFLOW: YES; ROT: 0; SEC: 1; SHIELDED: YES; SHROUDED: No; VER: 5; XY: (-1200,4850)
L24 = L_CMF_4P: ASSEMBLY: USB3_TYPEA; CDS_LIB: discrete; CDS_PART_NAME: L_CMF_4P_SMDA_012X010-90OHM,[ ],25%,0.2A,0.4OHM,[ ],102-0037-000; CDS_PHYS_PART_NAME: L_CMF_4P_SMDA_012X010-90OHM,[ ],25%,0.2A,0.4OHM,[ ],102-0037-000-102-0037-000,90OHM; CDS_SEC: 1; DC_RESISTANCE: 0.4ohm; DEVICE_TYPENAME: L_CMF_4P_SMDA_012X010-90OHM2502A04OHM102-0037-000-102-0037-00090OHM; DRAWING: @P3449_B01_LIB.P3449_B01(SCH_1):PAGE10; MAT: [ ]; MAX_CURRENT: 0.2A; NV_NAME: [ ]; NV_PN: 102-0037-000; PACK_TYPE: SMDA_012X010; PATH: I22; PHYS_PAGE: 10; PLACEMENT_NOTE: CoLayout with R167, R169; ROT: 6; SEC: 1; SIGNAL_MODEL: nv_ind_cmf_4p; SKU: NO STUFF; TOL: 25%; VER: 3; XY: (-6850,3100)
L26 = L_CMF_4P: ASSEMBLY: USB3_TYPEA; CDS_LIB: discrete; CDS_PART_NAME: L_CMF_4P_SMDA_012X010-90OHM,[ ],25%,0.2A,0.4OHM,[ ],102-0037-000; CDS_PHYS_PART_NAME: L_CMF_4P_SMDA_012X010-90OHM,[ ],25%,0.2A,0.4OHM,[ ],102-0037-000-102-0037-000,90OHM; CDS_SEC: 1; DC_RESISTANCE: 0.4ohm; DEVICE_TYPENAME: L_CMF_4P_SMDA_012X010-90OHM2502A04OHM102-0037-000-102-0037-00090OHM; DRAWING: @P3449_B01_LIB.P3449_B01(SCH_1):PAGE10; MAT: [ ]; MAX_CURRENT: 0.2A; NV_NAME: [ ]; NV_PN: 102-0037-000; PACK_TYPE: SMDA_012X010; PATH: I13; PHYS_PAGE: 10; PLACEMENT_NOTE: CoLayout with R167, R169; ROT: 0; SEC: 1; SEC_TYPE: SMDA_012X010; SIGNAL_MODEL: nv_ind_cmf_4p; SKU: NO STUFF; TOL: 25%; VER: 3; XY: (-6800,5950)
R287 = R#1: ASSEMBLY: USB3_TYPEA; CDS_LIB: discrete; CDS_PART_NAME: R_0402-0OHM,0.05 OHM,62.5MW,195-2655-000; CDS_PHYS_PART_NAME: R_0402-0OHM,0.05 OHM,62.5MW,195-2655-000-0OHM,195-2655-000; CDS_SEC: 1; CHIPS_PART_NAME: R; DEVICE_TYPENAME: R_0402-0OHM005OHM625MW195-2655-000-0OHM195-2655-000; DRAWING: @P3449_B01_LIB.P3449_B01(SCH_1):PAGE10; MAX_WATTAGE: 62.5mW; NV_PN: 195-2655-000; PATH: I21; PHYS_PAGE: 10; PLACEMENT_NOTE: CoLayout with L10; ROT: 0; SEC: 1; SIGNAL_MODEL: DEFAULT_RESISTOR_0.001OHM_2_1; TOL: 0.05 ohm; VER: 1; XY: (-6850,3250)
R288 = R#1: ASSEMBLY: USB3_TYPEA; CDS_LIB: discrete; CDS_PART_NAME: R_0402-0OHM,0.05 OHM,62.5MW,195-2655-000; CDS_PHYS_PART_NAME: R_0402-0OHM,0.05 OHM,62.5MW,195-2655-000-0OHM,195-2655-000; CDS_SEC: 1; CHIPS_PART_NAME: R; DEVICE_TYPENAME: R_0402-0OHM005OHM625MW195-2655-000-0OHM195-2655-000; DRAWING: @P3449_B01_LIB.P3449_B01(SCH_1):PAGE10; MAX_WATTAGE: 62.5mW; NV_PN: 195-2655-000; PATH: I23; PHYS_PAGE: 10; PLACEMENT_NOTE: CoLayout with L10; ROT: 0; SEC: 1; SIGNAL_MODEL: DEFAULT_RESISTOR_0.001OHM_2_1; TOL: 0.05 ohm; VER: 1; XY: (-6850,2950)
R289 = R#1: ASSEMBLY: USB3_TYPEA; CDS_LIB: discrete; CDS_PART_NAME: R_0402-0OHM,0.05 OHM,62.5MW,195-2655-000; CDS_PHYS_PART_NAME: R_0402-0OHM,0.05 OHM,62.5MW,195-2655-000-0OHM,195-2655-000; CDS_SEC: 1; CHIPS_PART_NAME: R; DEVICE_TYPENAME: R_0402-0OHM005OHM625MW195-2655-000-0OHM195-2655-000; DRAWING: @P3449_B01_LIB.P3449_B01(SCH_1):PAGE10; MAX_WATTAGE: 62.5mW; NV_PN: 195-2655-000; PATH: I7; PHYS_PAGE: 10; PLACEMENT_NOTE: CoLayout with L10; ROT: 0; SEC: 1; SIGNAL_MODEL: DEFAULT_RESISTOR_0.001OHM_2_1; TOL: 0.05 ohm; VER: 1; XY: (-6800,6100)
R290 = R#1: ASSEMBLY: USB3_TYPEA; CDS_LIB: discrete; CDS_PART_NAME: R_0402-0OHM,0.05 OHM,62.5MW,195-2655-000; CDS_PHYS_PART_NAME: R_0402-0OHM,0.05 OHM,62.5MW,195-2655-000-0OHM,195-2655-000; CDS_SEC: 1; CHIPS_PART_NAME: R; DEVICE_TYPENAME: R_0402-0OHM005OHM625MW195-2655-000-0OHM195-2655-000; DRAWING: @P3449_B01_LIB.P3449_B01(SCH_1):PAGE10; MAX_WATTAGE: 62.5mW; NV_PN: 195-2655-000; PATH: I12; PHYS_PAGE: 10; PLACEMENT_NOTE: CoLayout with L10; ROT: 0; SEC: 1; SIGNAL_MODEL: DEFAULT_RESISTOR_0.001OHM_2_1; TOL: 0.05 ohm; VER: 1; XY: (-6800,5800)

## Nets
GND: C127.2 C131.2 C326.2 C331.1 C335.2 C336.2 D4.3(GND1) D5.3(GND1) D6.3(GND1) D7.3(GND1) D8.3(GND1) D9.3(GND1) J32.4(GND1) J32.7(GND2) J32.13(GND3) J32.16(GND4) J32.19(MT1) J32.20(MT2) J32.21(MT3) J32.22(MT4) J33.4(GND1) J33.7(GND2) J33.13(GND3) J33.16(GND4) J33.19(MT1) J33.20(MT2) J33.21(MT3) J33.22(MT4) R270.1 R481.2 U21.8(GND) U21.9(PAD) ; also on sheet 1 3 4 5 6 7 8 9 10 11 12 15 16 19
VDD_5V_IN: C127.1 C131.1 U21.3(VIN1) U21.4(VIN2) ; also on sheet 3 4 7 10 11 12 15 19
VDD_USB_VBUSTYPEA: C326.1 C335.1 C336.1 J32.1(VBUS0) J32.10(VBUS1) J33.1(VBUS0) J33.10(VBUS1) U21.5(VOUT)
DSP1_DN: L10.2 R167.1 ; also on sheet 15
DSP1_DP: L10.1 R169.1 ; also on sheet 15
DSP1_SSRX_N: D9.2(2A) D9.9(2B) J32.14(SSRXN1) ; also on sheet 15
DSP1_SSRX_P: D9.1(1A) D9.10(1B) J32.15(SSRXP1) ; also on sheet 15
DSP1_SSTX_N: C192.1 ; also on sheet 15
DSP1_SSTX_P: C190.1 ; also on sheet 15
DSP2_DN: L20.2 R275.1 ; also on sheet 15
DSP2_DP: L20.1 R276.1 ; also on sheet 15
DSP2_SSRX_N: D9.5(4A) D9.6(4B) J32.5(SSRXN0) ; also on sheet 15
DSP2_SSRX_P: D9.4(3A) D9.7(3B) J32.6(SSRXP0) ; also on sheet 15
DSP2_SSTX_N: C191.1 ; also on sheet 15
DSP2_SSTX_P: C189.1 ; also on sheet 15
DSP3_DN: L26.2 R289.1 ; also on sheet 15
DSP3_DP: L26.1 R290.1 ; also on sheet 15
DSP3_SSRX_N: D7.2(2A) D7.9(2B) J33.14(SSRXN1) ; also on sheet 15
DSP3_SSRX_P: D7.1(1A) D7.10(1B) J33.15(SSRXP1) ; also on sheet 15
DSP3_SSTX_N: C201.1 ; also on sheet 15
DSP3_SSTX_P: C198.1 ; also on sheet 15
DSP4_DN: L24.1 R287.1 ; also on sheet 15
DSP4_DP: L24.2 R288.1 ; also on sheet 15
DSP4_SSRX_N: D6.5(4A) D6.6(4B) J33.5(SSRXN0) ; also on sheet 15
DSP4_SSRX_P: D6.4(3A) D6.7(3B) J33.6(SSRXP0) ; also on sheet 15
DSP4_SSTX_N: C200.1 ; also on sheet 15
DSP4_SSTX_P: C196.1 ; also on sheet 15
DSP1234_PWR: R270.2 U21.2(EN_UVLO) ; also on sheet 15
USB1_J32_N: D8.1(1A) D8.10(1B) J32.11(DN1) L10.3 R167.2
USB1_J32_P: D8.2(2A) D8.9(2B) J32.12(DP1) L10.4 R169.2
USB1_J33_N: D6.1(1A) D6.10(1B) J33.11(DN1) L26.3 R289.2
USB1_J33_P: D6.2(2A) D6.9(2B) J33.12(DP1) L26.4 R290.2
USB2_J32_N: D8.4(3A) D8.7(3B) J32.2(DN0) L20.3 R275.2
USB2_J32_P: D8.5(4A) D8.6(4B) J32.3(DP0) L20.4 R276.2
USB2_J33_N: D7.5(4A) D7.6(4B) J33.2(DN0) L24.4 R287.2
USB2_J33_P: D7.4(3A) D7.7(3B) J33.3(DP0) L24.3 R288.2
USB_TYPEA_ILIM: R481.1 U21.7(ILIM)
USB_TYPEA_OCP: U21.6(FLT_BAR) ; also on sheet 15
USB_TYPEA_SS: C331.2 U21.1(DVDT)
USBSS_TX_J32_1_N: C192.2 D4.1(1A) D4.10(1B) J32.17(SSTXN1)
USBSS_TX_J32_1_P: C190.2 D4.2(2A) D4.9(2B) J32.18(SSTXP1)
USBSS_TX_J32_2_N: C191.2 D4.4(3A) D4.7(3B) J32.8(SSTXN0)
USBSS_TX_J32_2_P: C189.2 D4.5(4A) D4.6(4B) J32.9(SSTXP0)
USBSS_TX_J33_1_N: C201.2 D5.4(3A) D5.7(3B) J33.17(SSTXN1)
USBSS_TX_J33_1_P: C198.2 D5.5(4A) D5.6(4B) J33.18(SSTXP1)
USBSS_TX_J33_2_N: C200.2 D5.1(1A) D5.10(1B) J33.8(SSTXN0)
USBSS_TX_J33_2_P: C196.2 D5.2(2A) D5.9(2B) J33.9(SSTXP0)

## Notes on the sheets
sheet 13
- A
- B
- C
- D
- E
- F
- G
- H
- USB 3.0 TYPE A x2 CONNECTOR (2 OF 2)
- 1
- 1
- Co-locate Resistors to avoid
  stubs
- PCB CO-LAYOUT
- 2
- 2
- 3
- 3
- Co-locate Resistors to avoid
  stubs
- PCB CO-LAYOUT
- 4
- 4
- 5
- 5
- NVIDIA CORPORATION
- 2701 SAN TOMAS
  EXPRESSWAY
- ASSEMBLY
- <ASSEMBLY_DESCRIPTION>
- SANTA CLARA, CA 95050, USA
- PAGE DETAIL
- USB3.1 Type-A x2
  (B)
- NV_PN
- 600-13449-BASE-400
- ALL NVIDIA DESIGN SPECIFICATIONS, REFERENCE SPECIFICATIONS, REFERENCE BOARDS, FILES, DRAWINGS, DIAGNOSTICS, LISTS AND OTHER DOCUMENTS OR INFORMATION (TOGETHER AND SEPARATELY, 'MATERIALS') ARE BEING PROVIDED 'AS IS'. THE MATERIALS
  MAY
- CONTAIN KNOWN AND UNKNOWN VIOLATIONS OR DEVIATIONS OF INDUSTRY STANDARDS AND SPECIFICATIONS. NVIDIA MAKES NO WARRANTIES, EXPRESSED, IMPLIED, STATUTORY OR OTHERWISE WITH RESPECT TO THE MATERIALS OR OTHERWISE, AND EXPRESSLY DISCLAIMS
  ALL
- PCB REV
- P3449-B01
- PAGE
- 10 OF 23
- IMPLIED WARRANTIES INCLUDING, WITHOUT LIMITATION, THE WARRANTIES OF DESIGN, OF NONINFRINGEMENT, MERCHANTABILITY OR FITNESS FOR A PARTICULAR PURPOSE, OR ARISING FROM A COURSE OF DEALING, TRADE USAGE, TRADE PRACTICE, OR INDUSTRY
  STANDARDS.
- BOM REV
- M
- DATE
- 08-OCT-2022
- A
- B
- C
- D
- E
- F
- G
- H
sheet 14
- A
- B
- C
- D
- E
- F
- G
- H
- USB 3.0 TYPE A x2 CONNECTOR (1 OF 2)
- 1
- 1
- Place close to J32 and J33
- 1kohm for 1.9A limit
- 2.18A trip (7.5% higher)
- 2
- Co-locate Resistors to avoid
  stubs
- 2
- PCB CO-LAYOUT
- 3
- 3
- Co-locate Resistors to avoid
  stubs
- PCB CO-LAYOUT
- 4
- 4
- 5
- 5
- NVIDIA CORPORATION
- 2701 SAN TOMAS
  EXPRESSWAY
- ASSEMBLY
- <ASSEMBLY_DESCRIPTION>
- SANTA CLARA, CA 95050, USA
- PAGE DETAIL
- USB3.1 Type-A x2
  (A)
- NV_PN
- 600-13449-BASE-400
- ALL NVIDIA DESIGN SPECIFICATIONS, REFERENCE SPECIFICATIONS, REFERENCE BOARDS, FILES, DRAWINGS, DIAGNOSTICS, LISTS AND OTHER DOCUMENTS OR INFORMATION (TOGETHER AND SEPARATELY, 'MATERIALS') ARE BEING PROVIDED 'AS IS'. THE MATERIALS
  MAY
- CONTAIN KNOWN AND UNKNOWN VIOLATIONS OR DEVIATIONS OF INDUSTRY STANDARDS AND SPECIFICATIONS. NVIDIA MAKES NO WARRANTIES, EXPRESSED, IMPLIED, STATUTORY OR OTHERWISE WITH RESPECT TO THE MATERIALS OR OTHERWISE, AND EXPRESSLY DISCLAIMS
  ALL
- PCB REV
- P3449-B01
- PAGE
- 9 OF 23
- IMPLIED WARRANTIES INCLUDING, WITHOUT LIMITATION, THE WARRANTIES OF DESIGN, OF NONINFRINGEMENT, MERCHANTABILITY OR FITNESS FOR A PARTICULAR PURPOSE, OR ARISING FROM A COURSE OF DEALING, TRADE USAGE, TRADE PRACTICE, OR INDUSTRY
  STANDARDS.
- BOM REV
- M
- DATE
- 08-OCT-2022
- A
- B
- C
- D
- E
- F
- G
- H
